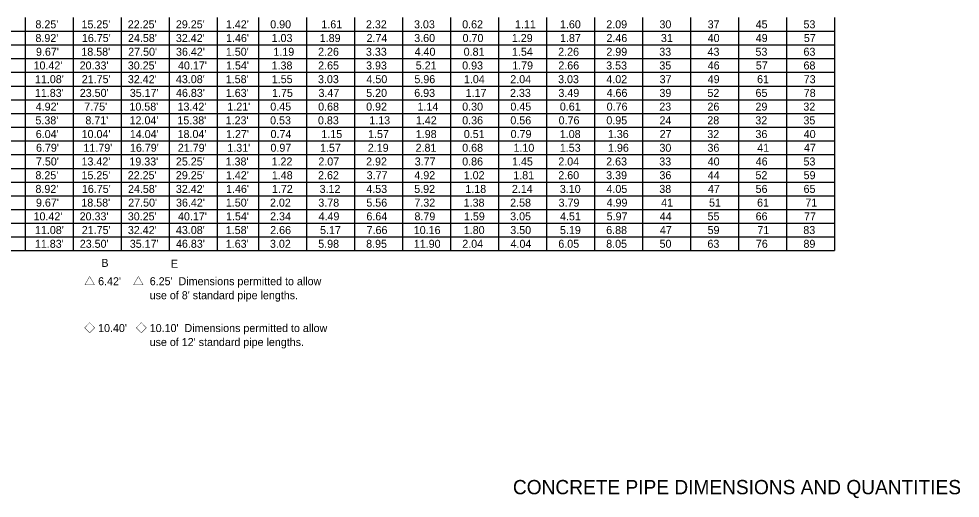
# Model space of a CAD drawing. Extents: x 1.7 to 14.6, y 0 to 8.4.
# Drawn here: x 6.33 to 14.56, y 0.02 to 4.22 of the extents above; entities that cross this region are included whole.
import ezdxf

# ---------------------------------------------------------------- set-up
doc = ezdxf.new("R2010")
doc.units = 0
doc.layers.add('Table', color=7, linetype='Continuous')
doc.layers.add('TextStructures', color=7, linetype='Continuous')

msp = doc.modelspace()

# ---------------------------------------------------------------- linework, layer by layer
at = {"layer": 'Table'}
for points in [[(6.38, 4.23), (6.38, 4.11), (6.38, 3.99), (6.38, 3.87), (6.38, 3.75), (6.38, 3.63), (6.38, 3.51), (6.38, 3.39), (6.38, 3.27), (6.38, 3.15), (6.38, 3.03), (6.38, 2.91), (6.38, 2.79), (6.38, 2.67), (6.38, 2.55), (6.38, 2.43), (6.38, 2.31), (6.38, 2.19)], [(6.8, 4.23), (6.8, 4.11), (6.8, 3.99), (6.8, 3.87), (6.8, 3.75), (6.8, 3.63), (6.8, 3.51), (6.8, 3.39), (6.8, 3.27), (6.8, 3.15), (6.8, 3.03), (6.8, 2.91), (6.8, 2.79), (6.8, 2.67), (6.8, 2.55), (6.8, 2.43), (6.8, 2.31), (6.8, 2.19)], [(7.22, 4.23), (7.22, 4.11), (7.22, 3.99), (7.22, 3.87), (7.22, 3.75), (7.22, 3.63), (7.22, 3.51), (7.22, 3.39), (7.22, 3.27), (7.22, 3.15), (7.22, 3.03), (7.22, 2.91), (7.22, 2.79), (7.22, 2.67), (7.22, 2.55), (7.22, 2.43), (7.22, 2.31), (7.22, 2.19)], [(7.64, 4.23), (7.64, 4.11), (7.64, 3.99), (7.64, 3.87), (7.64, 3.75), (7.64, 3.63), (7.64, 3.51), (7.64, 3.39), (7.64, 3.27), (7.64, 3.15), (7.64, 3.03), (7.64, 2.91), (7.64, 2.79), (7.64, 2.67), (7.64, 2.55), (7.64, 2.43), (7.64, 2.31), (7.64, 2.19)], [(8.06, 4.23), (8.06, 4.11), (8.06, 3.99), (8.06, 3.87), (8.06, 3.75), (8.06, 3.63), (8.06, 3.51), (8.06, 3.39), (8.06, 3.27), (8.06, 3.15), (8.06, 3.03), (8.06, 2.91), (8.06, 2.79), (8.06, 2.67), (8.06, 2.55), (8.06, 2.43), (8.06, 2.31), (8.06, 2.19)], [(8.42, 4.23), (8.42, 4.11), (8.42, 3.99), (8.42, 3.87), (8.42, 3.75), (8.42, 3.63), (8.42, 3.51), (8.42, 3.39), (8.42, 3.27), (8.42, 3.15), (8.42, 3.03), (8.42, 2.91), (8.42, 2.79), (8.42, 2.67), (8.42, 2.55), (8.42, 2.43), (8.42, 2.31), (8.42, 2.19)], [(8.84, 4.23), (8.84, 4.11), (8.84, 3.99), (8.84, 3.87), (8.84, 3.75), (8.84, 3.63), (8.84, 3.51), (8.84, 3.39), (8.84, 3.27), (8.84, 3.15), (8.84, 3.03), (8.84, 2.91), (8.84, 2.79), (8.84, 2.67), (8.84, 2.55), (8.84, 2.43), (8.84, 2.31), (8.84, 2.19)], [(9.26, 4.23), (9.26, 4.11), (9.26, 3.99), (9.26, 3.87), (9.26, 3.75), (9.26, 3.63), (9.26, 3.51), (9.26, 3.39), (9.26, 3.27), (9.26, 3.15), (9.26, 3.03), (9.26, 2.91), (9.26, 2.79), (9.26, 2.67), (9.26, 2.55), (9.26, 2.43), (9.26, 2.31), (9.26, 2.19)], [(9.68, 4.23), (9.68, 4.11), (9.68, 3.99), (9.68, 3.87), (9.68, 3.75), (9.68, 3.63), (9.68, 3.51), (9.68, 3.39), (9.68, 3.27), (9.68, 3.15), (9.68, 3.03), (9.68, 2.91), (9.68, 2.79), (9.68, 2.67), (9.68, 2.55), (9.68, 2.43), (9.68, 2.31), (9.68, 2.19)], [(10.1, 4.23), (10.1, 4.11), (10.1, 3.99), (10.1, 3.87), (10.1, 3.75), (10.1, 3.63), (10.1, 3.51), (10.1, 3.39), (10.1, 3.27), (10.1, 3.15), (10.1, 3.03), (10.1, 2.91), (10.1, 2.79), (10.1, 2.67), (10.1, 2.55), (10.1, 2.43), (10.1, 2.31), (10.1, 2.19)], [(10.52, 4.23), (10.52, 4.11), (10.52, 3.99), (10.52, 3.87), (10.52, 3.75), (10.52, 3.63), (10.52, 3.51), (10.52, 3.39), (10.52, 3.27), (10.52, 3.15), (10.52, 3.03), (10.52, 2.91), (10.52, 2.79), (10.52, 2.67), (10.52, 2.55), (10.52, 2.43), (10.52, 2.31), (10.52, 2.19)], [(10.94, 4.23), (10.94, 4.11), (10.94, 3.99), (10.94, 3.87), (10.94, 3.75), (10.94, 3.63), (10.94, 3.51), (10.94, 3.39), (10.94, 3.27), (10.94, 3.15), (10.94, 3.03), (10.94, 2.91), (10.94, 2.79), (10.94, 2.67), (10.94, 2.55), (10.94, 2.43), (10.94, 2.31), (10.94, 2.19)], [(11.36, 4.23), (11.36, 4.11), (11.36, 3.99), (11.36, 3.87), (11.36, 3.75), (11.36, 3.63), (11.36, 3.51), (11.36, 3.39), (11.36, 3.27), (11.36, 3.15), (11.36, 3.03), (11.36, 2.91), (11.36, 2.79), (11.36, 2.67), (11.36, 2.55), (11.36, 2.43), (11.36, 2.31), (11.36, 2.19)], [(11.78, 4.23), (11.78, 4.11), (11.78, 3.99), (11.78, 3.87), (11.78, 3.75), (11.78, 3.63), (11.78, 3.51), (11.78, 3.39), (11.78, 3.27), (11.78, 3.15), (11.78, 3.03), (11.78, 2.91), (11.78, 2.79), (11.78, 2.67), (11.78, 2.55), (11.78, 2.43), (11.78, 2.31), (11.78, 2.19)], [(12.2, 4.23), (12.2, 4.11), (12.2, 3.99), (12.2, 3.87), (12.2, 3.75), (12.2, 3.63), (12.2, 3.51), (12.2, 3.39), (12.2, 3.27), (12.2, 3.15), (12.2, 3.03), (12.2, 2.91), (12.2, 2.79), (12.2, 2.67), (12.2, 2.55), (12.2, 2.43), (12.2, 2.31), (12.2, 2.19)], [(12.62, 4.23), (12.62, 4.11), (12.62, 3.99), (12.62, 3.87), (12.62, 3.75), (12.62, 3.63), (12.62, 3.51), (12.62, 3.39), (12.62, 3.27), (12.62, 3.15), (12.62, 3.03), (12.62, 2.91), (12.62, 2.79), (12.62, 2.67), (12.62, 2.55), (12.62, 2.43), (12.62, 2.31), (12.62, 2.19)], [(13.04, 4.23), (13.04, 4.11), (13.04, 3.99), (13.04, 3.87), (13.04, 3.75), (13.04, 3.63), (13.04, 3.51), (13.04, 3.39), (13.04, 3.27), (13.04, 3.15), (13.04, 3.03), (13.04, 2.91), (13.04, 2.79), (13.04, 2.67), (13.04, 2.55), (13.04, 2.43), (13.04, 2.31), (13.04, 2.19)], [(13.46, 4.23), (13.46, 4.11), (13.46, 3.99), (13.46, 3.87), (13.46, 3.75), (13.46, 3.63), (13.46, 3.51), (13.46, 3.39), (13.46, 3.27), (13.46, 3.15), (13.46, 3.03), (13.46, 2.91), (13.46, 2.79), (13.46, 2.67), (13.46, 2.55), (13.46, 2.43), (13.46, 2.31), (13.46, 2.19)], [(6.02, 4.11), (6.38, 4.11), (6.8, 4.11), (7.22, 4.11), (7.64, 4.11), (8.06, 4.11), (8.42, 4.11), (8.84, 4.11), (9.26, 4.11), (9.68, 4.11), (10.1, 4.11), (10.52, 4.11), (10.94, 4.11), (11.36, 4.11), (11.78, 4.11), (12.2, 4.11), (12.62, 4.11), (13.04, 4.11), (13.46, 4.11)], [(6.02, 3.99), (6.38, 3.99), (6.8, 3.99), (7.22, 3.99), (7.64, 3.99), (8.06, 3.99), (8.42, 3.99), (8.84, 3.99), (9.26, 3.99), (9.68, 3.99), (10.1, 3.99), (10.52, 3.99), (10.94, 3.99), (11.36, 3.99), (11.78, 3.99), (12.2, 3.99), (12.62, 3.99), (13.04, 3.99), (13.46, 3.99)], [(6.02, 3.87), (6.38, 3.87), (6.8, 3.87), (7.22, 3.87), (7.64, 3.87), (8.06, 3.87), (8.42, 3.87), (8.84, 3.87), (9.26, 3.87), (9.68, 3.87), (10.1, 3.87), (10.52, 3.87), (10.94, 3.87), (11.36, 3.87), (11.78, 3.87), (12.2, 3.87), (12.62, 3.87), (13.04, 3.87), (13.46, 3.87)], [(6.02, 3.75), (6.38, 3.75), (6.8, 3.75), (7.22, 3.75), (7.64, 3.75), (8.06, 3.75), (8.42, 3.75), (8.84, 3.75), (9.26, 3.75), (9.68, 3.75), (10.1, 3.75), (10.52, 3.75), (10.94, 3.75), (11.36, 3.75), (11.78, 3.75), (12.2, 3.75), (12.62, 3.75), (13.04, 3.75), (13.46, 3.75)], [(6.02, 3.63), (6.38, 3.63), (6.8, 3.63), (7.22, 3.63), (7.64, 3.63), (8.06, 3.63), (8.42, 3.63), (8.84, 3.63), (9.26, 3.63), (9.68, 3.63), (10.1, 3.63), (10.52, 3.63), (10.94, 3.63), (11.36, 3.63), (11.78, 3.63), (12.2, 3.63), (12.62, 3.63), (13.04, 3.63), (13.46, 3.63)], [(6.02, 3.51), (6.38, 3.51), (6.8, 3.51), (7.22, 3.51), (7.64, 3.51), (8.06, 3.51), (8.42, 3.51), (8.84, 3.51), (9.26, 3.51), (9.68, 3.51), (10.1, 3.51), (10.52, 3.51), (10.94, 3.51), (11.36, 3.51), (11.78, 3.51), (12.2, 3.51), (12.62, 3.51), (13.04, 3.51), (13.46, 3.51)], [(6.02, 3.39), (6.38, 3.39), (6.8, 3.39), (7.22, 3.39), (7.64, 3.39), (8.06, 3.39), (8.42, 3.39), (8.84, 3.39), (9.26, 3.39), (9.68, 3.39), (10.1, 3.39), (10.52, 3.39), (10.94, 3.39), (11.36, 3.39), (11.78, 3.39), (12.2, 3.39), (12.62, 3.39), (13.04, 3.39), (13.46, 3.39)], [(6.02, 3.27), (6.38, 3.27), (6.8, 3.27), (7.22, 3.27), (7.64, 3.27), (8.06, 3.27), (8.42, 3.27), (8.84, 3.27), (9.26, 3.27), (9.68, 3.27), (10.1, 3.27), (10.52, 3.27), (10.94, 3.27), (11.36, 3.27), (11.78, 3.27), (12.2, 3.27), (12.62, 3.27), (13.04, 3.27), (13.46, 3.27)], [(6.02, 3.15), (6.38, 3.15), (6.8, 3.15), (7.22, 3.15), (7.64, 3.15), (8.06, 3.15), (8.42, 3.15), (8.84, 3.15), (9.26, 3.15), (9.68, 3.15), (10.1, 3.15), (10.52, 3.15), (10.94, 3.15), (11.36, 3.15), (11.78, 3.15), (12.2, 3.15), (12.62, 3.15), (13.04, 3.15), (13.46, 3.15)], [(6.02, 3.03), (6.38, 3.03), (6.8, 3.03), (7.22, 3.03), (7.64, 3.03), (8.06, 3.03), (8.42, 3.03), (8.84, 3.03), (9.26, 3.03), (9.68, 3.03), (10.1, 3.03), (10.52, 3.03), (10.94, 3.03), (11.36, 3.03), (11.78, 3.03), (12.2, 3.03), (12.62, 3.03), (13.04, 3.03), (13.46, 3.03)], [(6.02, 2.91), (6.38, 2.91), (6.8, 2.91), (7.22, 2.91), (7.64, 2.91), (8.06, 2.91), (8.42, 2.91), (8.84, 2.91), (9.26, 2.91), (9.68, 2.91), (10.1, 2.91), (10.52, 2.91), (10.94, 2.91), (11.36, 2.91), (11.78, 2.91), (12.2, 2.91), (12.62, 2.91), (13.04, 2.91), (13.46, 2.91)], [(6.02, 2.79), (6.38, 2.79), (6.8, 2.79), (7.22, 2.79), (7.64, 2.79), (8.06, 2.79), (8.42, 2.79), (8.84, 2.79), (9.26, 2.79), (9.68, 2.79), (10.1, 2.79), (10.52, 2.79), (10.94, 2.79), (11.36, 2.79), (11.78, 2.79), (12.2, 2.79), (12.62, 2.79), (13.04, 2.79), (13.46, 2.79)], [(6.02, 2.67), (6.38, 2.67), (6.8, 2.67), (7.22, 2.67), (7.64, 2.67), (8.06, 2.67), (8.42, 2.67), (8.84, 2.67), (9.26, 2.67), (9.68, 2.67), (10.1, 2.67), (10.52, 2.67), (10.94, 2.67), (11.36, 2.67), (11.78, 2.67), (12.2, 2.67), (12.62, 2.67), (13.04, 2.67), (13.46, 2.67)], [(6.02, 2.55), (6.38, 2.55), (6.8, 2.55), (7.22, 2.55), (7.64, 2.55), (8.06, 2.55), (8.42, 2.55), (8.84, 2.55), (9.26, 2.55), (9.68, 2.55), (10.1, 2.55), (10.52, 2.55), (10.94, 2.55), (11.36, 2.55), (11.78, 2.55), (12.2, 2.55), (12.62, 2.55), (13.04, 2.55), (13.46, 2.55)], [(6.02, 2.43), (6.38, 2.43), (6.8, 2.43), (7.22, 2.43), (7.64, 2.43), (8.06, 2.43), (8.42, 2.43), (8.84, 2.43), (9.26, 2.43), (9.68, 2.43), (10.1, 2.43), (10.52, 2.43), (10.94, 2.43), (11.36, 2.43), (11.78, 2.43), (12.2, 2.43), (12.62, 2.43), (13.04, 2.43), (13.46, 2.43)], [(6.02, 2.31), (6.38, 2.31), (6.8, 2.31), (7.22, 2.31), (7.64, 2.31), (8.06, 2.31), (8.42, 2.31), (8.84, 2.31), (9.26, 2.31), (9.68, 2.31), (10.1, 2.31), (10.52, 2.31), (10.94, 2.31), (11.36, 2.31), (11.78, 2.31), (12.2, 2.31), (12.62, 2.31), (13.04, 2.31), (13.46, 2.31)], [(6.02, 2.19), (6.38, 2.19), (6.8, 2.19), (7.22, 2.19), (7.64, 2.19), (8.06, 2.19), (8.42, 2.19), (8.84, 2.19), (9.26, 2.19), (9.68, 2.19), (10.1, 2.19), (10.52, 2.19), (10.94, 2.19), (11.36, 2.19), (11.78, 2.19), (12.2, 2.19), (12.62, 2.19), (13.04, 2.19), (13.46, 2.19)]]:
    msp.add_lwpolyline(points, dxfattribs=at)

# ---------------------------------------------------------------- texts
for s, p in [("8.25'", (6.4706, 4.135)), ("15.25'", (6.8735, 4.135)), ("22.25'", (7.2779, 4.135)), ("29.25'", (7.699, 4.135)), ("1.42'", (8.1364, 4.135)), ('0.90', (8.5241, 4.135)), ('1.61', (8.9711, 4.135)), ('2.32', (9.3612, 4.135)), ('3.03', (9.7817, 4.135)), ('30', (11.9279, 4.135)), ('37', (12.3497, 4.135)), ('45', (12.7696, 4.135)), ('53', (13.1878, 4.135)), ("8.92'", (6.4706, 4.015)), ("16.75'", (6.8768, 4.015)), ("24.58'", (7.2798, 4.015)), ("32.42'", (7.6988, 4.015)), ("1.46'", (8.1375, 4.015)), ('1.03', (8.5363, 4.015)), ('1.89', (8.9569, 4.015)), ('2.74', (9.3664, 4.015)), ('3.60', (9.7835, 4.015)), ('31', (11.9409, 4.015)), ('40', (12.35, 4.015)), ('49', (12.7701, 4.015)), ('57', (13.1909, 4.015)), ("9.67'", (6.4753, 3.895)), ("18.58'", (6.872, 3.895)), ("27.50'", (7.2818, 3.895)), ("36.42'", (7.6999, 3.895)), ("1.50'", (8.1359, 3.895)), ('1.19', (8.5516, 3.895)), ('2.26', (8.9426, 3.895)), ('3.33', (9.3611, 3.895)), ('4.40', (9.7866, 3.895)), ('33', (11.9266, 3.895)), ('43', (12.3488, 3.895)), ('53', (12.7678, 3.895)), ('63', (13.1878, 3.895)), ("10.42'", (6.4539, 3.775)), ("20.33'", (6.8572, 3.775)), ("30.25'", (7.2783, 3.775)), ("40.17'", (7.7173, 3.775)), ("1.54'", (8.1374, 3.775)), ('1.38', (8.5359, 3.775)), ('2.65', (8.9432, 3.775)), ('3.93', (9.3622, 3.775)), ('5.21', (9.7966, 3.775)), ('35', (11.9274, 3.775)), ('46', (12.3501, 3.775)), ('57', (12.7709, 3.775)), ('68', (13.188, 3.775)), ("11.08'", (6.4662, 3.655)), ("21.75'", (6.8758, 3.655)), ("32.42'", (7.2788, 3.655)), ("43.08'", (7.6991, 3.655)), ("1.58'", (8.1351, 3.655)), ('1.55', (8.5377, 3.655)), ('3.03', (8.9417, 3.655)), ('4.50', (9.3656, 3.655)), ('5.96', (9.7848, 3.655)), ('37', (11.9297, 3.655)), ('49', (12.3501, 3.655)), ('61', (12.782, 3.655)), ('73', (13.19, 3.655)), ("11.83'", (6.4656, 3.535)), ("23.50'", (6.8583, 3.535)), ("35.17'", (7.2957, 3.535)), ("46.83'", (7.6997, 3.535)), ("1.63'", (8.1353, 3.535)), ('1.75', (8.5399, 3.535)), ('3.47', (8.9463, 3.535)), ('5.20', (9.3635, 3.535)), ('6.93', (9.7834, 3.535)), ('39', (11.928, 3.535)), ('52', (12.3479, 3.535)), ('65', (12.7686, 3.535)), ('78', (13.1902, 3.535)), ("4.92'", (6.4729, 3.415)), ("7.75'", (6.8975, 3.415)), ("10.58'", (7.2927, 3.415)), ("13.42'", (7.7133, 3.415)), ("1.21'", (8.1488, 3.415)), ('0.45', (8.5247, 3.415)), ('0.68', (8.9431, 3.415)), ('0.92', (9.3629, 3.415)), ('1.14', (9.8121, 3.415)), ('23', (11.9267, 3.415)), ('26', (12.3481, 3.415)), ('29', (12.7681, 3.415)), ('32', (13.1867, 3.415)), ("5.38'", (6.4705, 3.295)), ("8.71'", (6.9074, 3.295)), ("12.04'", (7.2939, 3.295)), ("15.38'", (7.7121, 3.295)), ("1.23'", (8.1342, 3.295)), ('0.53', (8.5228, 3.295)), ('0.83', (8.9415, 3.295)), ('1.13', (9.3903, 3.295)), ('1.42', (9.7979, 3.295)), ('24', (11.9285, 3.295)), ('28', (12.3469, 3.295)), ('32', (12.7667, 3.295)), ('35', (13.1874, 3.295)), ("6.04'", (6.4735, 3.175)), ("10.04'", (6.8745, 3.175)), ("14.04'", (7.296, 3.175)), ("18.04'", (7.7137, 3.175)), ("1.27'", (8.1376, 3.175)), ('0.74', (8.5269, 3.175)), ('1.15', (8.9711, 3.175)), ('1.57', (9.3799, 3.175)), ('1.98', (9.7971, 3.175)), ('27', (11.9298, 3.175)), ('32', (12.3467, 3.175)), ('36', (12.768, 3.175)), ('40', (13.19, 3.175)), ("6.79'", (6.4753, 3.055)), ("11.79'", (6.8903, 3.055)), ("16.79'", (7.2969, 3.055)), ("21.79'", (7.7158, 3.055)), ("1.31'", (8.1487, 3.055)), ('0.97', (8.526, 3.055)), ('1.57', (8.9599, 3.055)), ('2.19', (9.3771, 3.055)), ('2.81', (9.7953, 3.055)), ('30', (11.9279, 3.055)), ('36', (12.348, 3.055)), ('41', (12.783, 3.055)), ('47', (13.1919, 3.055)), ("7.50'", (6.4747, 2.935)), ("13.42'", (6.8733, 2.935)), ("19.33'", (7.2923, 2.935)), ("25.25'", (7.699, 2.935)), ("1.38'", (8.134, 2.935)), ('1.22', (8.5358, 2.935)), ('2.07', (8.9449, 2.935)), ('2.92', (9.3624, 2.935)), ('3.77', (9.7876, 2.935)), ('33', (11.9266, 2.935)), ('40', (12.35, 2.935)), ('46', (12.7701, 2.935)), ('53', (13.1878, 2.935)), ("8.25'", (6.4706, 2.815)), ("15.25'", (6.8735, 2.815)), ("22.25'", (7.2779, 2.815)), ("29.25'", (7.699, 2.815)), ("1.42'", (8.1364, 2.815)), ('1.48', (8.538, 2.815)), ('2.62', (8.9424, 2.815)), ('3.77', (9.3676, 2.815)), ('4.92', (9.7845, 2.815)), ('36', (11.928, 2.815)), ('44', (12.3506, 2.815)), ('52', (12.7679, 2.815)), ('59', (13.1891, 2.815)), ("8.92'", (6.4706, 2.695)), ("16.75'", (6.8768, 2.695)), ("24.58'", (7.2798, 2.695)), ("32.42'", (7.6988, 2.695)), ("1.46'", (8.1375, 2.695)), ('1.72', (8.5392, 2.695)), ('3.12', (8.9558, 2.695)), ('4.53', (9.3644, 2.695)), ('5.92', (9.7835, 2.695)), ('38', (11.9268, 2.695)), ('47', (12.3519, 2.695)), ('56', (12.7691, 2.695)), ('65', (13.1886, 2.695)), ("9.67'", (6.4753, 2.575)), ("18.58'", (6.872, 2.575)), ("27.50'", (7.2818, 2.575)), ("36.42'", (7.6999, 2.575)), ("1.50'", (8.1359, 2.575)), ('2.02', (8.5219, 2.575)), ('3.78', (8.9447, 2.575)), ('5.56', (9.3647, 2.575)), ('7.32', (9.7846, 2.575)), ('41', (11.943, 2.575)), ('51', (12.362, 2.575)), ('61', (12.782, 2.575)), ('71', (13.2043, 2.575)), ("10.42'", (6.4539, 2.455)), ("20.33'", (6.8572, 2.455)), ("30.25'", (7.2783, 2.455)), ("40.17'", (7.7173, 2.455)), ("1.54'", (8.1374, 2.455)), ('2.34', (8.523, 2.455)), ('4.49', (8.9468, 2.455)), ('6.64', (9.3652, 2.455)), ('8.79', (9.7857, 2.455)), ('44', (11.9306, 2.455)), ('55', (12.3486, 2.455)), ('66', (12.7691, 2.455)), ('77', (13.1931, 2.455)), ("11.08'", (6.4662, 2.335)), ("21.75'", (6.8758, 2.335)), ("32.42'", (7.2788, 2.335)), ("43.08'", (7.6991, 2.335)), ("1.58'", (8.1351, 2.335)), ('2.66', (8.5237, 2.335)), ('5.17', (8.9599, 2.335)), ('7.66', (9.367, 2.335)), ('10.16', (9.7792, 2.335)), ('47', (11.9319, 2.335)), ('59', (12.3491, 2.335)), ('71', (12.7843, 2.335)), ('83', (13.1865, 2.335)), ("11.83'", (6.4656, 2.215)), ("23.50'", (6.8583, 2.215)), ("35.17'", (7.2957, 2.215)), ("46.83'", (7.6997, 2.215)), ("1.63'", (8.1353, 2.215)), ('3.02', (8.5218, 2.215)), ('5.98', (8.9436, 2.215)), ('8.95', (9.3629, 2.215)), ('11.90', (9.7797, 2.215)), ('50', (11.929, 2.215)), ('63', (12.3478, 2.215)), ('76', (12.7714, 2.215)), ('89', (13.1878, 2.215)), ("△ 6.42'    △  6.25'  Dimensions permitted to allow ", (6.8971, 1.8875)), ("                      use of 8' standard pipe lengths.", (6.8971, 1.765)), ("◇ 10.40'   ◇ 10.10'  Dimensions permitted to allow ", (6.8971, 1.4778)), ("                      use of 12' standard pipe lengths.   ", (6.8971, 1.3553))]:
    msp.add_text(s, height=0.07, rotation=0, dxfattribs=at).set_placement(p)
for s, p in [('0.62', (10.2029, 4.135)), ('1.11', (10.6645, 4.135)), ('1.60', (11.0581, 4.135)), ('2.09', (11.4631, 4.135)), ('0.70', (10.2063, 4.015)), ('1.29', (10.6371, 4.015)), ('1.87', (11.0586, 4.015)), ('2.46', (11.4647, 4.015)), ('0.81', (10.2158, 3.895)), ('1.54', (10.6386, 3.895)), ('2.26', (11.0426, 3.895)), ('2.99', (11.4637, 3.895)), ('0.93', (10.2028, 3.775)), ('1.79', (10.6404, 3.775)), ('2.66', (11.0437, 3.775)), ('3.53', (11.4622, 3.775)), ('1.04', (10.2181, 3.655)), ('2.04', (10.6236, 3.655)), ('3.03', (11.0417, 3.655)), ('4.02', (11.4639, 3.655)), ('1.17', (10.2334, 3.535)), ('2.33', (10.6211, 3.535)), ('3.49', (11.0446, 3.535)), ('4.66', (11.4658, 3.535)), ('0.30', (10.2029, 3.415)), ('0.45', (10.6247, 3.415)), ('0.61', (11.0571, 3.415)), ('0.76', (11.4665, 3.415)), ('0.36', (10.203, 3.295)), ('0.56', (10.6242, 3.295)), ('0.76', (11.0465, 3.295)), ('0.95', (11.4637, 3.295)), ('0.51', (10.2171, 3.175)), ('0.79', (10.6265, 3.175)), ('1.08', (11.0565, 3.175)), ('1.36', (11.477, 3.175)), ('0.68', (10.2031, 3.055)), ('1.10', (10.6515, 3.055)), ('1.53', (11.0568, 3.055)), ('1.96', (11.4782, 3.055)), ('0.86', (10.2029, 2.935)), ('1.45', (10.6387, 2.935)), ('2.04', (11.0436, 2.935)), ('2.63', (11.4623, 2.935)), ('1.02', (10.2164, 2.815)), ('1.81', (10.6498, 2.815)), ('2.60', (11.0436, 2.815)), ('3.39', (11.4624, 2.815)), ('1.18', (10.2305, 2.695)), ('2.14', (10.6376, 2.695)), ('3.10', (11.0569, 2.695)), ('4.05', (11.4647, 2.695)), ('1.38', (10.2159, 2.575)), ('2.58', (10.6225, 2.575)), ('3.79', (11.0459, 2.575)), ('4.99', (11.4658, 2.575)), ('1.59', (10.2182, 2.455)), ('3.05', (10.6225, 2.455)), ('4.51', (11.0586, 2.455)), ('5.97', (11.4665, 2.455)), ('1.80', (10.2168, 2.335)), ('3.50', (10.6235, 2.335)), ('5.19', (11.0582, 2.335)), ('6.88', (11.4623, 2.335)), ('2.04', (10.2036, 2.215)), ('4.04', (10.6257, 2.215)), ('6.05', (11.0437, 2.215)), ('8.05', (11.4624, 2.215)), ('B', (7.0474, 2.048)), ('E', (7.6548, 2.0397))]:
    msp.add_text(s, height=0.07, dxfattribs=at).set_placement(p)
at = {"layer": 'TextStructures'}
msp.add_text('CONCRETE PIPE DIMENSIONS AND QUANTITIES', height=0.125, rotation=0, dxfattribs=at).set_placement((10.6466, 0.0588))

doc.saveas('drawing.dxf')
